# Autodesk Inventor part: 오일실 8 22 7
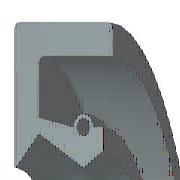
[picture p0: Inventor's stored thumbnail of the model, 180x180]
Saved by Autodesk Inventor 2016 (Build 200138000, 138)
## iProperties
IsCustomPart: 1
Created: 2012-02
Part Number: 오일실 8 22 7
Material: 고무
Description: 오일-실
Document SubType Name: Modeling
Standard: KS B 2804
Designer: mduedu
Standards Organization: KS
Language: ko-KR
Size Designation: D - 8 22 7
Categories: <MemberInstance><Categories><Category DisplayName="샤프트 부품" InternalName="7f7aeb1f-a693-4053-b835-cee3144e0d98" Mnemonic="SHFT"><Category DisplayName="실링" Intern
Density: 0.93 g/cm^3
Appearance: 고무 - 검은색 - 버전 1.1
Author: mduedu
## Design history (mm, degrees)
revolve "본체" stored, may be unused: angle "d17" = 90 deg
revolve "스프링1" stored, may be unused: angle "d18" = 90 deg
body "Solid1"
sketch "스케치1"
  geometry: L1 (0, 11)-(7, 11); L2 (7, 9.25)-(1.75, 9.25); L3 (1.75, 5.75)-(4.9, 4); L4 (4.9, 4)-(0, 4); L5 (0, 0)-(9.586, 0) reference; L6 (4.9, 4)-(6.3, 4.875); L7 (0, 18)-(0, -3) reference; L8 (-1.941, 0)-(11.507, 0) reference; L9 (4.2, 6.1)-(1.75, 6.59); L10 (1.75, 6.59)-(1.75, 9.25); L11 (0, 11)-(0, 4.088); L12 (4.9, 4)-(0, 4); L13 (1.75, 5.75)-(0.152, 4.028); L14 (7, 11)-(7, 9.25); L15 (5.6, 6.1)-(6.3, 6.1); L16 (6.3, 6.1)-(6.3, 4.875); C1 r 0.455 at (4.9, 6.1); A1 r 0.7 centre (4.9, 6.1) between (5.6, 6.1) and (4.2, 6.1); A2 r 0.088 centre (0.088, 4.088) between (0, 4.088) and (0.152, 4.028); 1 further point
  constraints: 28 end point, 5 horizontal alignment, 5 point on line, 4 point on circle, 4 vertical alignment, 3 centre point, 3 tangent, 2 collinear, 2 horizontal, 2 perpendicular, 1 coincident, 1 parallel
  dimensions: "d0" = 22 diameter of L1 L5 (= SD2); "d1" = 1.75 distance of L1.end L2.start (= SD); "d2" = 0.91 diameter of C1 (= SPDI); "d3" = 1.4 diameter of A1 (= SPDA); "d4" = 8 diameter of L3.end L5 (= NND); "d5" = 11.5 diameter of L3.start L5 (= TKDM); "d7" = 13.18 diameter of L9.end L5 (= TKDM + 0.24 x SWDT); "d8" = 1.75 distance between parallel lines of L11 L10 (= SD); "d9" = 4.9 distance from line of L11 C1.centre (= SPDST); "d10" = 12.2 diameter of C1.centre L5 (= HLDM); "d11" = 0.0875 radius of A2 (= 0.25 x LAB); "d12" = 6.3 distance between parallel lines of L11 L16 (= SDI); "d13" = 9.75 diameter of L6.end L5 (= ABDM); "d14" = 7 distance from line of L11 L1.end (= SWDT)
fillet "모깎기1" dims "d6" = 0.3 (= RR)
other parameters: "SD2" = 22 [user parameter; used in 1 equation term], "SWDT" = 7 [user parameter; used in 2 equation terms], "RR" = 0.3 [user parameter; used in 1 equation term], "SD" = 1.75 [user parameter; used in 2 equation terms], "NND" = 8 [user parameter; used in 1 equation term], "SPDA" = 1.4 [user parameter; used in 1 equation term], "SPDI" = 0.91 [user parameter; used in 1 equation term], "TKDM" = 11.5 [user parameter; used in 2 equation terms], "HLDM" = 12.2 [user parameter; used in 1 equation term], "ABDM" = 9.75 [user parameter; used in 1 equation term], "SDI" = 6.3 [user parameter; used in 1 equation term], "SPDST" = 4.9 [user parameter; used in 1 equation term], "LAB" = 0.35 [user parameter; used in 1 equation term], "d15" = 0, "d16" = 0, "d19" = 0
